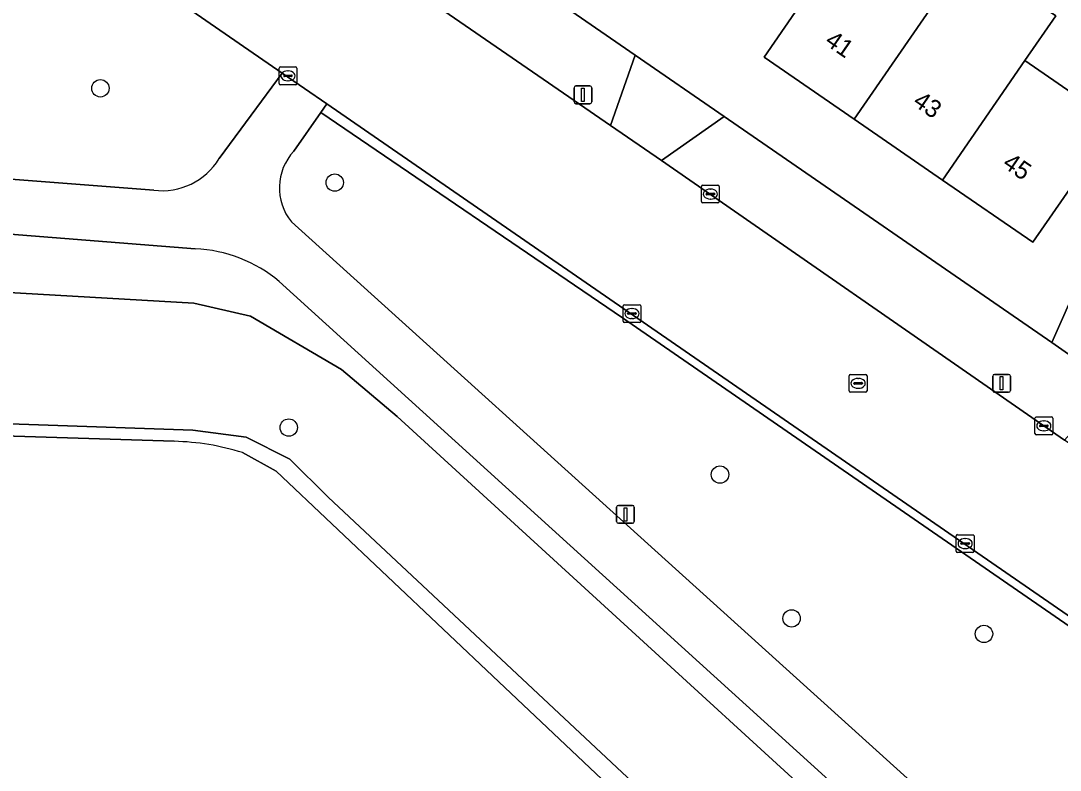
# Model space of a CAD drawing. Extents: x 162803 to 163818, y 381639 to 382475.
# Drawn here: x 163168.5 to 163226.9, y 381927.2 to 381969.4 of the extents above; entities that cross this region are included whole.
import ezdxf

# ---------------------------------------------------------------- set-up
doc = ezdxf.new("R2010")
doc.units = 0
for name, color, linetype in [('IMGEO_Boom', 7, 'Continuous'), ('IMGEO_Erf', 7, 'Continuous'), ('IMGEO_Groenvoorziening', 7, 'Continuous'), ('IMGEO_Kolk', 7, 'Continuous'), ('IMGEO_Lichtmast', 7, 'Continuous'), ('IMGEO_Loofbos', 7, 'Continuous'), ('IMGEO_Meer_plas_ven_vijver', 7, 'Continuous'), ('IMGEO_Oever', 7, 'Continuous'), ('IMGEO_Pand', 7, 'Continuous'), ('IMGEO_Pand_nummerreeks', 7, 'Continuous'), ('IMGEO_Rijbaan_lokaal_gesloten', 7, 'Continuous'), ('IMGEO_Rijbaan_lokaal_open', 7, 'Continuous'), ('IMGEO_Rioolput', 7, 'Continuous'), ('IMGEO_Voetpad_gesloten', 7, 'Continuous'), ('IMGEO_Voetpad_open', 7, 'Continuous')]:
    doc.layers.add(name, color=color, linetype=linetype)

msp = doc.modelspace()

# ---------------------------------------------------------------- linework, layer by layer
at = {"layer": 'IMGEO_Boom'}
for centre in [(163172.927, 381965.58), (163186.102, 381960.277), (163183.515, 381946.502), (163207.758, 381943.855), (163211.783, 381935.769), (163222.598, 381934.896)]:
    msp.add_circle(centre, 0.489, dxfattribs=at)
at = {"layer": 'IMGEO_Erf'}
for points in [[(163155.874, 382000), (163183.007, 381981.238), (163187.84, 381977.902), (163202.987, 381967.447), (163207.986, 381963.996), (163226.407, 381951.281), (163231.088, 381961.805)], [(163228.189, 381961.039), (163225.351, 381956.921), (163220.269, 381960.423), (163215.31, 381963.84), (163210.232, 381967.339), (163213.725, 381972.408), (163211.225, 381974.131), (163208.727, 381975.853), (163205.244, 381970.799), (163200.171, 381974.295), (163195.219, 381977.708), (163190.143, 381981.206), (163193.608, 381986.235), (163191.16, 381987.922), (163188.71, 381989.61), (163185.231, 381984.562), (163180.117, 381988.086), (163175.126, 381991.526), (163170.009, 381995.052), (163171.797, 381997.646), (163168.37, 382000)], [(163229.667, 381982.165), (163211.704, 381991.627), (163207.628, 381993.909), (163204.743, 381995.523), (163204.538, 381995.156), (163200.782, 381997.153), (163198.919, 381994.448), (163199.317, 381994.174), (163196.657, 381990.314), (163201.573, 381986.927), (163206.523, 381983.516), (163204.816, 381981.038), (163204.975, 381980.929), (163209.664, 381977.698), (163214.071, 381984.093), (163216.795, 381982.216), (163219.081, 381985.535), (163221.768, 381983.684), (163219.481, 381980.365), (163216.785, 381976.452), (163221.679, 381973.079), (163226.636, 381969.662), (163224.9, 381967.143), (163229.982, 381963.641)]]:
    msp.add_lwpolyline(points, dxfattribs=at)
at = {"layer": 'IMGEO_Groenvoorziening'}
for points in [[(163183.668, 381958.067), (163229.946, 381916.228), (163242.218, 381925.095), (163202.279, 381952.665), (163185.319, 381964.222), (163183.803, 381962.044)], [(163178.255, 381956.56), (163148.676, 381958.887)], [(163186.481, 381949.766), (163181.36, 381952.757), (163178.182, 381953.501), (163152.171, 381954.991)], [(163152.171, 381954.991), (163178.182, 381953.501), (163181.36, 381952.757), (163186.481, 381949.766), (163189.606, 381947.131), (163226.313, 381913.527), (163227.401, 381914.389), (163182.982, 381954.71)], [(163144.749, 381950.075), (163144.629, 381949.763), (163140.373, 381938.66), (163143.885, 381937.393), (163147.032, 381945.822), (163147.802, 381946.835), (163147.865, 381946.85), (163149.627, 381947.261), (163152.081, 381947.261), (163178.118, 381946.346), (163181.112, 381945.966), (163183.575, 381944.725), (163185.733, 381942.588), (163221.136, 381909.426), (163226.313, 381913.527), (163189.606, 381947.131), (163186.481, 381949.766)]]:
    msp.add_lwpolyline(points, dxfattribs=at)
for centre, radius, start, end in [((163185.995, 381959.979), 3.011, 136.70075, 219.41091), ((163177.876, 381948.628), 7.941, 49.98638, 87.26598)]:
    msp.add_arc(centre, radius, start, end, dxfattribs=at)
at = {"layer": 'IMGEO_Kolk'}
for p, q in [((163182.97, 381965.855), (163182.97, 381966.707)), ((163183.045, 381966.781), (163183.897, 381966.781)), ((163183.971, 381966.707), (163183.971, 381965.855)), ((163183.229, 381966.275), (163183.229, 381966.287)), ((163183.667, 381966.238), (163183.269, 381966.238)), ((163183.272, 381966.324), (163183.67, 381966.324)), ((163183.481, 381966.001), (163183.456, 381966.001)), ((163183.458, 381966.561), (163183.483, 381966.561)), ((163183.713, 381966.287), (163183.713, 381966.275)), ((163183.897, 381965.781), (163183.045, 381965.781)), ((163206.718, 381959.208), (163206.718, 381960.06)), ((163206.793, 381960.134), (163207.645, 381960.134)), ((163206.977, 381959.628), (163206.977, 381959.64)), ((163207.415, 381959.591), (163207.017, 381959.591)), ((163207.02, 381959.677), (163207.418, 381959.677)), ((163207.206, 381959.914), (163207.231, 381959.914)), ((163207.461, 381959.64), (163207.461, 381959.628)), ((163207.719, 381960.06), (163207.719, 381959.208)), ((163207.645, 381959.134), (163206.793, 381959.134)), ((163207.229, 381959.354), (163207.204, 381959.354)), ((163202.306, 381952.486), (163202.306, 381953.338)), ((163202.381, 381953.412), (163203.233, 381953.412)), ((163202.794, 381953.192), (163202.819, 381953.192)), ((163203.307, 381953.338), (163203.307, 381952.486)), ((163202.565, 381952.906), (163202.565, 381952.918)), ((163203.003, 381952.869), (163202.605, 381952.869)), ((163202.608, 381952.955), (163203.006, 381952.955)), ((163202.817, 381952.632), (163202.792, 381952.632)), ((163203.049, 381952.918), (163203.049, 381952.906)), ((163203.233, 381952.412), (163202.381, 381952.412)), ((163225.464, 381946.171), (163225.464, 381947.023)), ((163225.539, 381947.097), (163226.391, 381947.097)), ((163225.952, 381946.877), (163225.977, 381946.877)), ((163226.465, 381947.023), (163226.465, 381946.171)), ((163225.723, 381946.591), (163225.723, 381946.603)), ((163226.161, 381946.554), (163225.763, 381946.554)), ((163225.766, 381946.64), (163226.164, 381946.64)), ((163225.975, 381946.317), (163225.95, 381946.317)), ((163226.207, 381946.603), (163226.207, 381946.591)), ((163226.391, 381946.097), (163225.539, 381946.097)), ((163221.039, 381939.551), (163221.039, 381940.403)), ((163221.114, 381940.477), (163221.966, 381940.477)), ((163222.04, 381940.403), (163222.04, 381939.551)), ((163221.298, 381939.971), (163221.298, 381939.983)), ((163221.736, 381939.934), (163221.338, 381939.934)), ((163221.341, 381940.02), (163221.739, 381940.02)), ((163221.55, 381939.697), (163221.525, 381939.697)), ((163221.527, 381940.257), (163221.552, 381940.257)), ((163221.782, 381939.983), (163221.782, 381939.971)), ((163221.966, 381939.477), (163221.114, 381939.477))]:
    msp.add_line(p, q, dxfattribs=at)
for points in [[(163182.97, 381965.855), (163182.97, 381966.707)], [(163183.045, 381966.781), (163183.897, 381966.781)], [(163183.971, 381966.707), (163183.971, 381965.855)], [(163183.897, 381965.781), (163183.045, 381965.781)], [(163206.718, 381959.208), (163206.718, 381960.06)], [(163206.793, 381960.134), (163207.645, 381960.134)], [(163207.719, 381960.06), (163207.719, 381959.208)], [(163207.645, 381959.134), (163206.793, 381959.134)], [(163202.306, 381952.486), (163202.306, 381953.338)], [(163202.381, 381953.412), (163203.233, 381953.412)], [(163203.307, 381953.338), (163203.307, 381952.486)], [(163203.233, 381952.412), (163202.381, 381952.412)], [(163225.464, 381946.171), (163225.464, 381947.023)], [(163225.539, 381947.097), (163226.391, 381947.097)], [(163226.465, 381947.023), (163226.465, 381946.171)], [(163226.391, 381946.097), (163225.539, 381946.097)], [(163221.039, 381939.551), (163221.039, 381940.403)], [(163221.114, 381940.477), (163221.966, 381940.477)], [(163222.04, 381940.403), (163222.04, 381939.551)], [(163221.966, 381939.477), (163221.114, 381939.477)]]:
    msp.add_lwpolyline(points, dxfattribs=at)
for centre, radius, start, end in [((163183.047, 381966.705), 0.0765, 91.55205, 178.44795), ((163183.047, 381966.705), 0.0765, 91.55205, 178.44795), ((163183.895, 381966.705), 0.0765, 1.55205, 88.44795), ((163183.895, 381966.705), 0.0765, 1.55205, 88.44795), ((163183.269, 381966.284), 0.0403, 85.87752, 175.75265), ((163183.266, 381966.274), 0.0366, 178.93798, 274.71019), ((163183.67, 381966.281), 0.043, 264.86636, 352.45326), ((163183.674, 381966.286), 0.0386, 1.73085, 96.63898), ((163183.047, 381965.857), 0.0765, 181.55205, 268.44795), ((163183.047, 381965.857), 0.0765, 181.55205, 268.44795), ((163183.895, 381965.857), 0.0765, 271.55205, 358.44795), ((163183.895, 381965.857), 0.0765, 271.55205, 358.44795), ((163206.795, 381960.058), 0.0765, 91.55205, 178.44795), ((163206.795, 381960.058), 0.0765, 91.55205, 178.44795), ((163207.017, 381959.637), 0.0403, 85.87752, 175.75265), ((163207.014, 381959.627), 0.0366, 178.93798, 274.71019), ((163207.418, 381959.634), 0.043, 264.86636, 352.45326), ((163207.422, 381959.639), 0.0386, 1.73085, 96.63898), ((163207.643, 381960.058), 0.0765, 1.55205, 88.44795), ((163207.643, 381960.058), 0.0765, 1.55205, 88.44795), ((163206.795, 381959.21), 0.0765, 181.55205, 268.44795), ((163206.795, 381959.21), 0.0765, 181.55205, 268.44795), ((163207.643, 381959.21), 0.0765, 271.55205, 358.44795), ((163207.643, 381959.21), 0.0765, 271.55205, 358.44795), ((163202.383, 381953.336), 0.0765, 91.55205, 178.44795), ((163202.383, 381953.336), 0.0765, 91.55205, 178.44795), ((163203.231, 381953.336), 0.0765, 1.55205, 88.44795), ((163203.231, 381953.336), 0.0765, 1.55205, 88.44795), ((163202.605, 381952.915), 0.0403, 85.87752, 175.75265), ((163202.602, 381952.905), 0.0366, 178.93798, 274.71019), ((163203.006, 381952.912), 0.043, 264.86636, 352.45326), ((163203.01, 381952.917), 0.0386, 1.73085, 96.63898), ((163202.383, 381952.488), 0.0765, 181.55205, 268.44795), ((163202.383, 381952.488), 0.0765, 181.55205, 268.44795), ((163203.231, 381952.488), 0.0765, 271.55205, 358.44795), ((163203.231, 381952.488), 0.0765, 271.55205, 358.44795), ((163225.541, 381947.021), 0.0765, 91.55205, 178.44795), ((163225.541, 381947.021), 0.0765, 91.55205, 178.44795), ((163226.389, 381947.021), 0.0765, 1.55205, 88.44795), ((163226.389, 381947.021), 0.0765, 1.55205, 88.44795), ((163225.541, 381946.173), 0.0765, 181.55205, 268.44795), ((163225.541, 381946.173), 0.0765, 181.55205, 268.44795), ((163225.763, 381946.6), 0.0403, 85.87752, 175.75265), ((163225.76, 381946.59), 0.0366, 178.93798, 274.71019), ((163226.164, 381946.597), 0.043, 264.86636, 352.45326), ((163226.168, 381946.602), 0.0386, 1.73085, 96.63898), ((163226.389, 381946.173), 0.0765, 271.55205, 358.44795), ((163226.389, 381946.173), 0.0765, 271.55205, 358.44795), ((163221.116, 381940.401), 0.0765, 91.55205, 178.44795), ((163221.116, 381940.401), 0.0765, 91.55205, 178.44795), ((163221.964, 381940.401), 0.0765, 1.55205, 88.44795), ((163221.964, 381940.401), 0.0765, 1.55205, 88.44795), ((163221.338, 381939.98), 0.0403, 85.87752, 175.75265), ((163221.335, 381939.97), 0.0366, 178.93798, 274.71019), ((163221.739, 381939.977), 0.043, 264.86636, 352.45326), ((163221.743, 381939.982), 0.0386, 1.73085, 96.63898), ((163221.116, 381939.553), 0.0765, 181.55205, 268.44795), ((163221.116, 381939.553), 0.0765, 181.55205, 268.44795), ((163221.964, 381939.553), 0.0765, 271.55205, 358.44795), ((163221.964, 381939.553), 0.0765, 271.55205, 358.44795)]:
    msp.add_arc(centre, radius, start, end, dxfattribs=at)
for centre, major_axis, ratio, start_param, end_param in [((163183.457, 381966.281), (-0.387, 0.002), 0.722429, 4.712389, 7.853982), ((163183.482, 381966.281), (-0.39, 0.002), 0.717154, 1.570796, 4.712389), ((163207.205, 381959.634), (-0.387, 0.002), 0.722429, 4.712389, 7.853982), ((163207.23, 381959.634), (-0.39, 0.002), 0.717154, 1.570796, 4.712389), ((163202.793, 381952.912), (-0.387, 0.002), 0.722429, 4.712389, 7.853982), ((163202.818, 381952.912), (-0.39, 0.002), 0.717154, 1.570796, 4.712389), ((163225.951, 381946.597), (-0.387, 0.002), 0.722429, 4.712389, 7.853982), ((163225.976, 381946.597), (-0.39, 0.002), 0.717154, 1.570796, 4.712389), ((163221.526, 381939.977), (-0.387, 0.002), 0.722429, 4.712389, 7.853982), ((163221.551, 381939.977), (-0.39, 0.002), 0.717154, 1.570796, 4.712389)]:
    msp.add_ellipse(centre, major_axis=major_axis, ratio=ratio, start_param=start_param, end_param=end_param, dxfattribs=at)
at = {"layer": 'IMGEO_Lichtmast'}
for p, q in [((163199.555, 381964.816), (163199.555, 381965.616)), ((163199.555, 381965.616), (163199.555, 381964.816)), ((163199.655, 381965.716), (163200.445, 381965.716)), ((163200.445, 381965.716), (163199.655, 381965.716)), ((163200.545, 381965.616), (163200.545, 381964.816)), ((163200.545, 381964.816), (163200.545, 381965.616)), ((163200.445, 381964.716), (163199.655, 381964.716)), ((163199.655, 381964.716), (163200.445, 381964.716)), ((163223.091, 381948.589), (163223.091, 381949.389)), ((163223.091, 381949.389), (163223.091, 381948.589)), ((163223.191, 381949.489), (163223.981, 381949.489)), ((163223.981, 381949.489), (163223.191, 381949.489)), ((163224.081, 381949.389), (163224.081, 381948.589)), ((163224.081, 381948.589), (163224.081, 381949.389)), ((163223.981, 381948.489), (163223.191, 381948.489)), ((163223.191, 381948.489), (163223.981, 381948.489)), ((163202.047, 381942.119), (163202.837, 381942.119)), ((163202.837, 381942.119), (163202.047, 381942.119)), ((163201.947, 381941.219), (163201.947, 381942.019)), ((163201.947, 381942.019), (163201.947, 381941.219)), ((163202.937, 381942.019), (163202.937, 381941.219)), ((163202.937, 381941.219), (163202.937, 381942.019)), ((163202.837, 381941.119), (163202.047, 381941.119)), ((163202.047, 381941.119), (163202.837, 381941.119))]:
    msp.add_line(p, q, dxfattribs=at)
for points in [[(163199.975, 381965.591), (163200.125, 381965.591), (163200.125, 381964.841), (163199.975, 381964.841), (163199.975, 381965.591)], [(163223.511, 381949.364), (163223.661, 381949.364), (163223.661, 381948.614), (163223.511, 381948.614), (163223.511, 381949.364)], [(163202.367, 381941.994), (163202.517, 381941.994), (163202.517, 381941.244), (163202.367, 381941.244), (163202.367, 381941.994)]]:
    msp.add_lwpolyline(points, dxfattribs=at)
for centre, start, end in [((163199.655, 381965.616), 90, 180), ((163199.655, 381965.616), 90, 180), ((163200.445, 381965.616), 0, 90), ((163200.445, 381965.616), 360, 90), ((163199.655, 381964.816), 180, 270), ((163199.655, 381964.816), 180, 270), ((163200.445, 381964.816), 270, 0), ((163200.445, 381964.816), 270, 0), ((163223.191, 381949.389), 90, 180), ((163223.191, 381949.389), 90, 180), ((163223.981, 381949.389), 0, 90), ((163223.981, 381949.389), 360, 90), ((163223.191, 381948.589), 180, 270), ((163223.191, 381948.589), 180, 270), ((163223.981, 381948.589), 270, 0), ((163223.981, 381948.589), 270, 0), ((163202.047, 381942.019), 90, 180), ((163202.047, 381942.019), 90, 180), ((163202.837, 381942.019), 0, 90), ((163202.837, 381942.019), 360, 90), ((163202.047, 381941.219), 180, 270), ((163202.047, 381941.219), 180, 270), ((163202.837, 381941.219), 270, 0), ((163202.837, 381941.219), 270, 0)]:
    msp.add_arc(centre, 0.1, start, end, dxfattribs=at)
at = {"layer": 'IMGEO_Loofbos'}
for points in [[(163179.602, 381961.628), (163181.399, 381964.068), (163183.143, 381966.437), (163150.669, 381988.849)], [(163148.641, 381961.949), (163175.922, 381959.854)]]:
    msp.add_lwpolyline(points, dxfattribs=at)
msp.add_arc((163176.402, 381963.561), 3.738, 262.61756, 328.85664, dxfattribs=at)
at = {"layer": 'IMGEO_Meer_plas_ven_vijver'}
for points in [[(163177.081, 381945.727), (163150.697, 381946.553), (163149.353, 381946.35), (163149.1, 381946.375), (163148.45, 381945.664), (163148.174, 381945.714), (163148.095, 381945.71), (163147.714, 381945.069), (163144.825, 381937.054), (163143.549, 381933.513), (163127.421, 381888.768), (163127.312, 381887.704)], [(163195.333, 381932.205), (163182.807, 381944.052), (163180.916, 381945.091)], [(163259.056, 381871.934), (163220.2, 381908.685), (163195.333, 381932.205)]]:
    msp.add_lwpolyline(points, dxfattribs=at)
msp.add_arc((163176.768, 381931.958), 13.772, 72.47034, 88.69709, dxfattribs=at)
at = {"layer": 'IMGEO_Oever'}
for points in [[(163180.916, 381945.091), (163182.807, 381944.052), (163195.333, 381932.205), (163220.2, 381908.685), (163221.136, 381909.426), (163185.733, 381942.588), (163183.575, 381944.725), (163181.112, 381945.966), (163178.118, 381946.346), (163152.081, 381947.261), (163149.627, 381947.261), (163147.865, 381946.85), (163147.802, 381946.835), (163147.032, 381945.822), (163143.885, 381937.393)], [(163143.885, 381937.393), (163144.825, 381937.054), (163147.714, 381945.069), (163148.095, 381945.71), (163148.174, 381945.714), (163148.45, 381945.664), (163149.1, 381946.375), (163149.353, 381946.35), (163150.697, 381946.553), (163177.081, 381945.727)]]:
    msp.add_lwpolyline(points, dxfattribs=at)
msp.add_arc((163176.768, 381931.958), 13.772, 72.47034, 88.69709, dxfattribs=at)
at = {"layer": 'IMGEO_Pand'}
for points in [[(163221.679, 381973.079), (163216.785, 381976.452), (163219.481, 381980.365), (163216.795, 381982.216), (163211.225, 381974.131), (163213.725, 381972.408), (163210.232, 381967.339), (163215.31, 381963.84)], [(163221.679, 381973.079), (163215.31, 381963.84), (163220.269, 381960.423), (163224.9, 381967.143), (163226.636, 381969.662)], [(163220.269, 381960.423), (163225.351, 381956.921), (163228.189, 381961.039), (163229.982, 381963.641), (163224.9, 381967.143)]]:
    msp.add_lwpolyline(points, close=True, dxfattribs=at)
at = {"layer": 'IMGEO_Rijbaan_lokaal_gesloten'}
for points in [[(163147.613, 381998.289), (163145.683, 381999.556), (163142.323, 381994.518), (163146.202, 381991.939), (163146.746, 381991.578), (163150.669, 381988.849), (163183.143, 381966.437), (163185.654, 381964.704), (163234.179, 381931.215), (163243.291, 381924.954), (163246.695, 381929.842), (163245.694, 381930.515)], [(163243.932, 381934.221), (163230.147, 381943.717), (163227.132, 381945.793), (163225.965, 381946.597), (163204.468, 381961.524), (163201.611, 381963.498), (163184.354, 381975.377), (163181.471, 381977.362), (163171.343, 381984.279), (163151.372, 381998.08)]]:
    msp.add_lwpolyline(points, dxfattribs=at)
at = {"layer": 'IMGEO_Rijbaan_lokaal_open'}
msp.add_lwpolyline([(163260.108, 381913.315), (163243.291, 381924.954), (163234.179, 381931.215), (163185.654, 381964.704), (163185.319, 381964.222), (163202.279, 381952.665), (163242.218, 381925.095), (163254.385, 381916.696), (163256.97, 381914.946), (163276.348, 381901.602), (163294.84, 381888.868), (163306.85, 381880.597), (163310.399, 381878.067), (163312.858, 381876.368), (163356.676, 381846.092), (163356.953, 381846.517), (163345.097, 381854.658), (163328.942, 381865.735), (163312.423, 381877.143), (163295.088, 381889.16), (163266.914, 381908.622)], close=True, dxfattribs=at)
at = {"layer": 'IMGEO_Rioolput'}
for p, q in [((163215.022, 381948.561), (163215.022, 381949.413)), ((163215.097, 381949.487), (163215.949, 381949.487)), ((163215.51, 381949.267), (163215.535, 381949.267)), ((163216.023, 381949.413), (163216.023, 381948.561)), ((163215.949, 381948.487), (163215.097, 381948.487)), ((163215.281, 381948.981), (163215.281, 381948.993)), ((163215.719, 381948.944), (163215.321, 381948.944)), ((163215.324, 381949.03), (163215.722, 381949.03)), ((163215.533, 381948.707), (163215.508, 381948.707)), ((163215.765, 381948.993), (163215.765, 381948.981))]:
    msp.add_line(p, q, dxfattribs=at)
for points in [[(163215.022, 381948.561), (163215.022, 381949.413)], [(163215.097, 381949.487), (163215.949, 381949.487)], [(163216.023, 381949.413), (163216.023, 381948.561)], [(163215.949, 381948.487), (163215.097, 381948.487)]]:
    msp.add_lwpolyline(points, dxfattribs=at)
for centre, radius, start, end in [((163215.099, 381949.411), 0.0765, 91.55205, 178.44795), ((163215.099, 381949.411), 0.0765, 91.55205, 178.44795), ((163215.947, 381949.411), 0.0765, 1.55205, 88.44795), ((163215.947, 381949.411), 0.0765, 1.55205, 88.44795), ((163215.099, 381948.563), 0.0765, 181.55205, 268.44795), ((163215.099, 381948.563), 0.0765, 181.55205, 268.44795), ((163215.321, 381948.99), 0.0403, 85.87752, 175.75265), ((163215.318, 381948.98), 0.0366, 178.93798, 274.71019), ((163215.722, 381948.987), 0.043, 264.86636, 352.45326), ((163215.726, 381948.992), 0.0386, 1.73085, 96.63898), ((163215.947, 381948.563), 0.0765, 271.55205, 358.44795), ((163215.947, 381948.563), 0.0765, 271.55205, 358.44795)]:
    msp.add_arc(centre, radius, start, end, dxfattribs=at)
for centre, major_axis, ratio, start_param, end_param in [((163215.509, 381948.987), (-0.387, 0.002), 0.722429, 4.712389, 7.853982), ((163215.534, 381948.987), (-0.39, 0.002), 0.717154, 1.570796, 4.712389)]:
    msp.add_ellipse(centre, major_axis=major_axis, ratio=ratio, start_param=start_param, end_param=end_param, dxfattribs=at)
at = {"layer": 'IMGEO_Voetpad_gesloten'}
for points in [[(163144.532, 381962.703), (163134.127, 381965.619), (163124.319, 381968.044), (163122.824, 381968.413), (163121.916, 381966.144), (163128.16, 381964.586), (163133.587, 381963.232), (163141.132, 381961.053), (163148.676, 381958.887), (163178.255, 381956.56)], [(163183.803, 381962.044), (163185.319, 381964.222), (163185.654, 381964.704), (163183.143, 381966.437), (163181.399, 381964.068), (163179.602, 381961.628)], [(163175.922, 381959.854), (163148.641, 381961.949)], [(163242.335, 381905.028), (163229.946, 381916.228), (163183.668, 381958.067)], [(163182.982, 381954.71), (163227.401, 381914.389), (163234.624, 381907.833), (163252.421, 381891.921), (163255.061, 381889.85)]]:
    msp.add_lwpolyline(points, dxfattribs=at)
for centre, radius, start, end in [((163185.995, 381959.979), 3.011, 136.70075, 219.41091), ((163176.402, 381963.561), 3.738, 262.61756, 328.85664), ((163177.876, 381948.628), 7.941, 49.98638, 87.26598)]:
    msp.add_arc(centre, radius, start, end, dxfattribs=at)
at = {"layer": 'IMGEO_Voetpad_open'}
for points in [[(163201.611, 381963.498), (163202.987, 381967.447), (163187.84, 381977.902), (163184.354, 381975.377)], [(163201.611, 381963.498), (163204.468, 381961.524), (163207.986, 381963.996), (163202.987, 381967.447)], [(163207.986, 381963.996), (163204.468, 381961.524), (163225.965, 381946.597), (163227.132, 381945.793), (163229.876, 381948.886), (163227.718, 381950.375), (163226.407, 381951.281)]]:
    msp.add_lwpolyline(points, close=True, dxfattribs=at)
msp.add_lwpolyline([(163231.088, 381961.805), (163226.407, 381951.281), (163227.718, 381950.375)], dxfattribs=at)

# ---------------------------------------------------------------- texts
at = {"layer": 'IMGEO_Pand_nummerreeks'}
for s, p in [('41', (163213.594, 381968.083)), ('43', (163218.541, 381964.674)), ('45', (163223.581, 381961.201))]:
    msp.add_text(s, height=1, rotation=325.43057, dxfattribs=at).set_placement(p)

doc.saveas('drawing.dxf')
